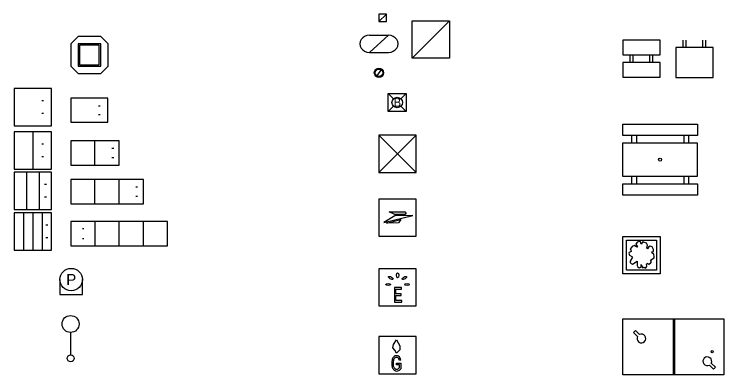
# Model space of a CAD drawing. Extents: x -1.5 to 18.2, y -66.6 to 3.3.
# Drawn here: x -1.52 to 17.51, y -24.67 to -14.99 of the extents above; entities that cross this region are included whole.
import ezdxf

# ---------------------------------------------------------------- set-up
doc = ezdxf.new("R2010")
doc.units = 0
for name, color, linetype in [('SOL_AFFLEUREMENT', 7, 'Continuous'), ('SOL_DIVERS_COFFRETS', 7, 'Continuous'), ('SOL_ELEC_COFFRET', 7, 'Continuous'), ('SOL_GAZ_COFFRET', 7, 'Continuous'), ('SOL_JEUX', 7, 'Continuous'), ('SOL_MOBILIER_DIVERS', 7, 'Continuous'), ('SOL_POTEAU', 7, 'Continuous'), ('SOL_SIGNALISATION_VERTICALE', 7, 'Continuous'), ('SOL_TELECOM_CHAMBRES', 7, 'Continuous')]:
    doc.layers.add(name, color=color, linetype=linetype)

# ---------------------------------------------------------------- blocks, each defined once
blk = doc.blocks.new('CONTAINER_FEUILLAGE_ENTERRE')
for points in [[(0.198, 0), (0.804, 0), (1.001, 0.197), (1.001, 0.803), (0.804, 1), (0.198, 1), (0.001, 0.803), (0.001, 0.197), (0.198, 0)], [(0.198, 0.197), (0.804, 0.197), (0.804, 0.803), (0.198, 0.803), (0.198, 0.197)], [(0.237, 0.236), (0.765, 0.236), (0.765, 0.764), (0.237, 0.764), (0.237, 0.236)]]:
    blk.add_lwpolyline(points)
blk = doc.blocks.new('PLAQUE_TELECOM_1_VOLET')
for points in [[(0, 0), (1, 0), (1, 0.65), (0, 0.65), (0, 0)], [(0.787, 0.437), (0.748, 0.437)], [(0.787, 0.197), (0.748, 0.197)]]:
    blk.add_lwpolyline(points)
blk = doc.blocks.new('PLAQUE_TELECOM_2_VOLETS')
for points in [[(0, 0), (1.3, 0), (1.3, 0.65), (0, 0.65), (0, 0)], [(0.65, 0), (0.65, 0.65)], [(1.1, 0.45), (1.157, 0.45)], [(1.1, 0.2), (1.157, 0.2)]]:
    blk.add_lwpolyline(points)
blk = doc.blocks.new('PLAQUE_TELECOM_3_VOLETS')
for points in [[(0, 0), (1.95, 0), (1.95, 0.65), (0, 0.65), (0, 0)], [(0.65, 0), (0.65, 0.65)], [(1.3, 0), (1.3, 0.65)], [(1.749, 0.449), (1.795, 0.449)], [(1.749, 0.201), (1.795, 0.201)]]:
    blk.add_lwpolyline(points)
blk = doc.blocks.new('PLAQUE_TELECOM_4_VOLETS')
for points in [[(0, 0), (2.6, 0), (2.6, 0.65), (0, 0.65), (0, 0)], [(0.655, 0), (0.655, 0.65)], [(1.3, 0), (1.3, 0.65)], [(1.955, 0), (1.955, 0.65)], [(0.317, 0.463), (0.348, 0.463)], [(0.348, 0.187), (0.317, 0.187)]]:
    blk.add_lwpolyline(points)
blk = doc.blocks.new('PANNEAU_STANDARD')
blk.add_line((0, 0.09), (0, 0.693))
for centre, radius in [((-0.003, 0.921), 0.228), ((0, -0.001), 0.0904)]:
    blk.add_circle(centre, radius)
blk = doc.blocks.new('POTEAU_CARRE')
blk.add_lwpolyline([(0, 0), (0.2, 0), (0.2, 0.2), (0, 0.2), (0, 0), (0.2, 0.2)])
blk = doc.blocks.new('BLOC_ANTISTATIONNEMENT')
for p, q in [((-0.256, 0.23), (0.256, 0.23)), ((-0.256, -0.23), (0.256, 0.23)), ((-0.256, -0.23), (0.258, -0.23))]:
    blk.add_line(p, q)
for centre, start_param, end_param in [((-0.256, 0), 1.570796, 4.712389), ((0.256, 0), 4.712389, 7.853982)]:
    blk.add_ellipse(centre, major_axis=(0.256, 0), ratio=0.899482, start_param=start_param, end_param=end_param)
blk = doc.blocks.new('POTEAU_AMOVIBLE')
blk.add_line((0.056, 0.083), (-0.056, -0.083))
for radius in [0.125, 0.1]:
    blk.add_circle((0, 0), radius)
blk = doc.blocks.new('ARMOIRE_DIVERS')
for points in [[(0, 0), (1, 0), (1, 1), (0, 1), (0, 0), (1, 1)], [(0, 1), (1, 0)]]:
    blk.add_lwpolyline(points)
blk = doc.blocks.new('BANC')
for points in [[(0, 0.6), (1, 0.6), (1, 1), (0, 1), (0, 0.6)], [(0.197, 0.4), (0.197, 0.6)], [(0.275, 0.4), (0.275, 0.6)], [(0.725, 0.4), (0.725, 0.6)], [(0.803, 0.4), (0.803, 0.6)], [(0, 0), (1, 0), (1, 0.4), (0, 0.4), (0, 0)]]:
    blk.add_lwpolyline(points)
blk = doc.blocks.new('TABLE_BANC')
for p, q in [((0.235, 1.6), (0.235, 1.4)), ((0.365, 1.6), (0.365, 1.4)), ((1.634, 1.6), (1.634, 1.4)), ((1.764, 1.6), (1.764, 1.4)), ((0.235, 0.501), (0.235, 0.301)), ((0.365, 0.501), (0.365, 0.301)), ((1.634, 0.501), (1.634, 0.301)), ((1.764, 0.501), (1.764, 0.301))]:
    blk.add_line(p, q)
for points in [[(0, 1.901), (2, 1.901), (2, 1.6), (0, 1.6)], [(0, 1.4), (1.999, 1.4), (1.999, 0.501), (0, 0.501)], [(0, 0.301), (2, 0.301), (2, 0), (0, 0)]]:
    blk.add_lwpolyline(points, close=True)
blk.add_circle((1, 0.951), 0.0396)
blk = doc.blocks.new('JARDINIERE')
for points in [[(1, 0), (0, 0), (0, 1), (1, 1)], [(0.9, 0.1), (0.1, 0.1), (0.1, 0.9), (0.9, 0.9)]]:
    blk.add_lwpolyline(points, close=True)
blk.add_lwpolyline([(0.379, 0.711), (0.317, 0.759), (0.252, 0.733), (0.198, 0.661), (0.212, 0.64), (0.228, 0.598), (0.172, 0.57), (0.165, 0.552), (0.179, 0.496), (0.247, 0.468), (0.258, 0.447), (0.201, 0.339), (0.201, 0.307), (0.228, 0.279), (0.258, 0.262), (0.383, 0.335), (0.39, 0.3), (0.383, 0.223), (0.403, 0.185), (0.443, 0.157), (0.489, 0.181), (0.496, 0.251), (0.518, 0.185), (0.542, 0.16), (0.575, 0.174), (0.621, 0.153), (0.644, 0.213), (0.634, 0.251), (0.657, 0.283), (0.7, 0.255), (0.743, 0.286), (0.77, 0.318), (0.739, 0.367), (0.842, 0.426), (0.842, 0.454), (0.836, 0.524), (0.792, 0.556), (0.783, 0.587), (0.822, 0.598), (0.822, 0.65), (0.786, 0.72), (0.733, 0.741), (0.69, 0.713), (0.667, 0.671), (0.644, 0.689), (0.66, 0.772), (0.634, 0.821), (0.542, 0.86), (0.518, 0.835), (0.496, 0.793), (0.476, 0.856), (0.456, 0.867), (0.386, 0.846), (0.347, 0.793), (0.397, 0.723), (0.379, 0.711)])
blk = doc.blocks.new('TABLE_PING_PONG')
for p, q in [((1.355, 1.504), (1.355, 0)), ((1.389, 1.504), (1.389, 0))]:
    blk.add_line(p, q)
blk.add_lwpolyline([(2.709, 0), (0, 0), (0, 1.504), (2.709, 1.504)], close=True)
for points in [[(0.445, 1.081), (0.338, 1.187), (0.286, 1.134), (0.394, 1.029)], [(2.323, 0.259), (2.43, 0.153), (2.482, 0.206), (2.374, 0.311)]]:
    blk.add_lwpolyline(points)
blk.add_circle((2.396, 0.62), 0.0302)
for centre, start, end in [((0.5, 0.976), 153.5416, 117.4222), ((2.268, 0.364), 333.5416, 297.4222)]:
    blk.add_arc(centre, 0.118, start, end)
blk = doc.blocks.new('BLOC_ANTISTATIONNEMENT RECTANGULAIRE')
blk.add_line((0, 0), (1, 1))
blk.add_lwpolyline([(0, 1), (1, 1), (1, 0), (0, 0)], close=True)
blk = doc.blocks.new('ARMOIRE_GAZ')
for p, q in [((0.369, 0.695), (0.385, 0.785)), ((0.385, 0.785), (0.466, 0.914)), ((0.466, 0.914), (0.518, 0.83)), ((0.518, 0.83), (0.556, 0.748)), ((0.428, 0.638), (0.369, 0.695)), ((0.468, 0.558), (0.428, 0.638)), ((0.558, 0.645), (0.468, 0.558)), ((0.556, 0.748), (0.558, 0.645)), ((0.474, 0.237), (0.474, 0.284)), ((0.474, 0.284), (0.585, 0.284)), ((0.551, 0.237), (0.474, 0.237)), ((0.551, 0.164), (0.551, 0.237)), ((0.585, 0.284), (0.585, 0.137))]:
    blk.add_line(p, q)
blk.add_lwpolyline([(0, 0), (1, 0), (1, 1), (0, 1)], close=True)
blk.add_lwpolyline([(0.581, 0.367), (0.55, 0.354)])
for centre, radius, start, end in [((0.692, 0.281), 0.351, 162.5715, 180.4501), ((0.506, 0.345), 0.154, 131.5629, 164.6148), ((0.539, 0.32), 0.158, 149.2129, 164.7119), ((0.472, 0.377), 0.108, 89.2702, 129.215), ((0.477, 0.357), 0.0852, 121.935, 149.2439), ((0.472, 0.364), 0.0766, 88.5701, 121.024), ((0.475, 0.387), 0.0984, 59.1152, 90.7358), ((0.474, 0.374), 0.0664, 57.4649, 90.5684), ((0.473, 0.371), 0.0699, 26.717, 57.82), ((0.475, 0.388), 0.0974, 27.209, 58.8768), ((0.361, 0.322), 0.192, 9.7601, 24.7048), ((0.36, 0.335), 0.224, 8.3577, 25.8411), ((0.667, 0.274), 0.326, 179.2701, 198.1669), ((0.678, 0.284), 0.301, 165.1111, 180.4621), ((0.659, 0.275), 0.282, 178.6774, 196.9454), ((0.492, 0.224), 0.107, 196.5046, 231.0074), ((0.503, 0.217), 0.152, 197.0312, 230.1174), ((0.476, 0.187), 0.112, 230.8912, 270.1492), ((0.475, 0.204), 0.0813, 231.9503, 269.4315), ((0.473, 0.208), 0.0847, 270.6197, 302.236), ((0.475, 0.188), 0.113, 270.4541, 300.4307), ((0.461, 0.237), 0.116, 299.691, 321.0713), ((0.429, 0.262), 0.2, 300.9197, 321.2187)]:
    blk.add_arc(centre, radius, start, end)
blk = doc.blocks.new('BOITE_POSTALE')
for points in [[(0, 0), (1, 0), (1, 1), (0, 1)], [(0.271, 0.658), (0.706, 0.658), (0.726, 0.632), (0.691, 0.584), (0.424, 0.581)], [(0.131, 0.371), (0.91, 0.559), (0.428, 0.552), (0.131, 0.371)], [(0.2, 0.355), (0.585, 0.45), (0.524, 0.361)]]:
    blk.add_lwpolyline(points, close=True)
blk = doc.blocks.new('BORNE_PUISAGE')
blk.add_lwpolyline([(-0.3, 0), (-0.3, -0.4), (0.3, -0.4), (0.3, 0)])
blk.add_circle((0, 0), 0.3)
blk.add_text('P', height=0.3).set_placement((-0.131, -0.15))
blk = doc.blocks.new('BORNE_TELESCOPIQUE')
for p, q in [((0.141, 0.339), (0, 0.48)), ((0, 0.48), (0.48, 0.48)), ((0.339, 0.339), (0.48, 0.48)), ((0.48, 0.48), (0.48, 0)), ((0.141, 0.141), (0, 0)), ((0.339, 0.141), (0.48, 0))]:
    blk.add_line(p, q)
blk.add_lwpolyline([(0, 0.48), (0.48, 0.48), (0.48, 0), (0, 0)], close=True)
blk.add_circle((0.24, 0.24), 0.14)
blk.add_text('B', height=0.225).set_placement((0.144, 0.13))
blk = doc.blocks.new('ARMOIRE_ELECTRIQUE')
for p, q in [((0, 1), (0, 0)), ((1, 1), (0, 1)), ((1, 0), (1, 1)), ((0.416, 0.495), (0.416, 0.099)), ((0.607, 0.495), (0.416, 0.495)), ((0.451, 0.327), (0.451, 0.448)), ((0.451, 0.448), (0.607, 0.448)), ((0.607, 0.448), (0.607, 0.495)), ((0.597, 0.327), (0.451, 0.327)), ((0.451, 0.146), (0.451, 0.28)), ((0.451, 0.28), (0.597, 0.28)), ((0.597, 0.28), (0.597, 0.327)), ((0, 0), (1, 0)), ((0.416, 0.099), (0.613, 0.099)), ((0.613, 0.146), (0.451, 0.146)), ((0.613, 0.099), (0.613, 0.146))]:
    blk.add_line(p, q)
for centre, major_axis in [((0.317, 0.751), (0.0575, -0.0364)), ((0.5, 0.825), (0, 0.0681)), ((0.683, 0.751), (-0.0575, -0.0364)), ((0.247, 0.577), (0.0681, 0)), ((0.753, 0.577), (-0.0681, 0))]:
    blk.add_ellipse(centre, major_axis=major_axis, ratio=0.414634)
blk = doc.blocks.new('PLAQUE_TELECOM_DIM1X1_1_VOLET')
for points in [[(0, 0), (1, 0), (1, 1), (0, 1), (0, 0)], [(0.787, 0.67), (0.737, 0.67)], [(0.787, 0.33), (0.737, 0.33)]]:
    blk.add_lwpolyline(points)
blk = doc.blocks.new('PLAQUE_TELECOM_DIM1X1_2_VOLETS')
blk.add_line((0.5, 1), (0.5, 0))
for points in [[(0, 0), (1, 0), (1, 1), (0, 1), (0, 0)], [(0.787, 0.67), (0.737, 0.67)], [(0.787, 0.33), (0.737, 0.33)]]:
    blk.add_lwpolyline(points)
blk = doc.blocks.new('PLAQUE_TELECOM_DIM1X1_3_VOLETS')
for p, q in [((0.33, 1), (0.33, 0)), ((0.67, 1), (0.67, 0))]:
    blk.add_line(p, q)
for points in [[(0, 0), (1, 0), (1, 1), (0, 1), (0, 0)], [(0.862, 0.67), (0.812, 0.67)], [(0.862, 0.33), (0.812, 0.33)]]:
    blk.add_lwpolyline(points)
blk = doc.blocks.new('PLAQUE_TELECOM_DIM1X1_4_VOLETS')
for p, q in [((0.25, 1), (0.25, 0)), ((0.5, 1), (0.5, 0)), ((0.75, 1), (0.75, 0))]:
    blk.add_line(p, q)
for points in [[(0, 0), (1, 0), (1, 1), (0, 1), (0, 0)], [(0.9, 0.67), (0.85, 0.67)], [(0.9, 0.33), (0.85, 0.33)]]:
    blk.add_lwpolyline(points)
blk = doc.blocks.new('BANC_SIMPLE')
blk.add_line((1, 0), (1, 0.611))
for points in [[(0.197, 0.8), (0.197, 1)], [(0.275, 0.8), (0.275, 1)], [(0.725, 0.8), (0.725, 1)], [(0.803, 0.8), (0.803, 1)], [(0, 0), (1, 0), (1, 0.8), (0, 0.8), (0, 0)]]:
    blk.add_lwpolyline(points)

msp = doc.modelspace()

# ---------------------------------------------------------------- block references
at = {"layer": 'SOL_AFFLEUREMENT'}
for name, p in [('CONTAINER_FEUILLAGE_ENTERRE', (0, -16.586)), ('BORNE_PUISAGE', (0.012, -22.113))]:
    msp.add_blockref(name, p, dxfattribs=at)
at = {"layer": 'SOL_DIVERS_COFFRETS'}
msp.add_blockref('ARMOIRE_DIVERS', (8.267, -19.239), dxfattribs=at)
at = {"layer": 'SOL_ELEC_COFFRET'}
msp.add_blockref('ARMOIRE_ELECTRIQUE', (8.267, -22.821), dxfattribs=at)
at = {"layer": 'SOL_GAZ_COFFRET'}
msp.add_blockref('ARMOIRE_GAZ', (8.267, -24.642), dxfattribs=at)
at = {"layer": 'SOL_JEUX'}
msp.add_blockref('TABLE_PING_PONG', (14.805, -24.669), dxfattribs=at)
at = {"layer": 'SOL_MOBILIER_DIVERS'}
for name, p in [('BLOC_ANTISTATIONNEMENT RECTANGULAIRE', (9.16, -16.173)), ('BLOC_ANTISTATIONNEMENT', (8.267, -15.787)), ('BANC', (14.805, -16.684)), ('BANC_SIMPLE', (16.227, -16.689)), ('TABLE_BANC', (14.805, -19.846)), ('BOITE_POSTALE', (8.267, -20.951)), ('JARDINIERE', (14.805, -21.958))]:
    msp.add_blockref(name, p, dxfattribs=at)
at = {"layer": 'SOL_POTEAU'}
for name, p in [('POTEAU_CARRE', (8.267, -15.191)), ('POTEAU_AMOVIBLE', (8.267, -16.562)), ('BORNE_TELESCOPIQUE', (8.516, -17.601))]:
    msp.add_blockref(name, p, dxfattribs=at)
at = {"layer": 'SOL_SIGNALISATION_VERTICALE'}
msp.add_blockref('PANNEAU_STANDARD', (0, -24.226), dxfattribs=at)
at = {"layer": 'SOL_TELECOM_CHAMBRES'}
for name, p in [('PLAQUE_TELECOM_DIM1X1_1_VOLET', (-1.515, -17.988)), ('PLAQUE_TELECOM_1_VOLET', (0, -17.893)), ('PLAQUE_TELECOM_DIM1X1_2_VOLETS', (-1.515, -19.147)), ('PLAQUE_TELECOM_2_VOLETS', (0, -19.04)), ('PLAQUE_TELECOM_DIM1X1_3_VOLETS', (-1.515, -20.234)), ('PLAQUE_TELECOM_3_VOLETS', (0, -20.077)), ('PLAQUE_TELECOM_DIM1X1_4_VOLETS', (-1.515, -21.321)), ('PLAQUE_TELECOM_4_VOLETS', (0, -21.203))]:
    msp.add_blockref(name, p, dxfattribs=at)

doc.saveas('drawing.dxf')
